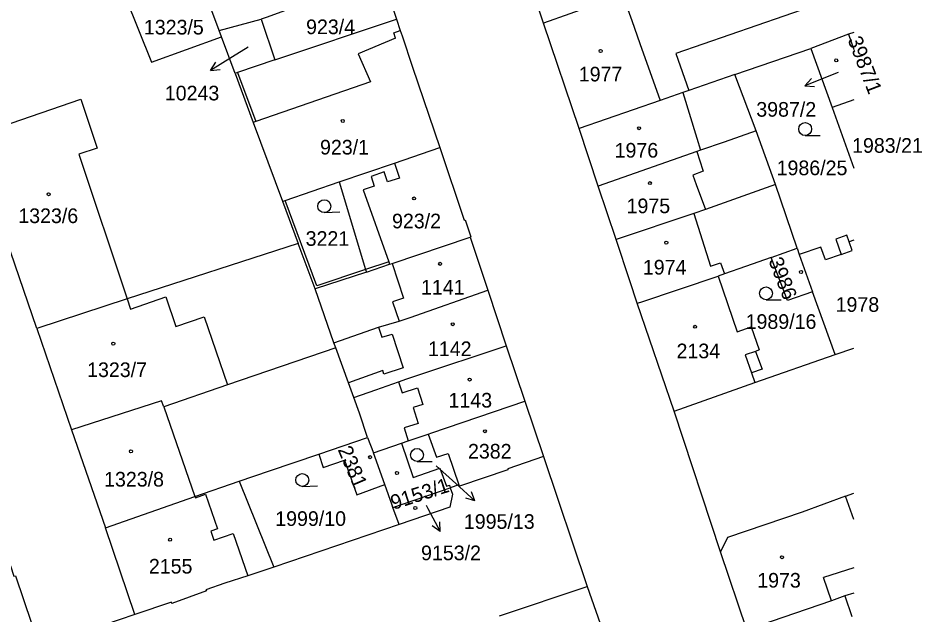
# Model space of a CAD drawing. Extents: x -564952 to -564307, y -1202373 to -1201847.
# Drawn here: x -564411.7 to -564306.7, y -1202091.3 to -1202022 of the extents above; entities that cross this region are included whole.
import ezdxf

# ---------------------------------------------------------------- set-up
doc = ezdxf.new("R2010")
doc.units = 0
for name, color, linetype in [('Hranice parcel', 7, 'Continuous'), ('Parcelní čísla', 7, 'Continuous'), ('Pop  PČ popisy', 7, 'Continuous'), ('Vnitřní kresba', 7, 'Continuous'), ('Značky budov', 7, 'Continuous'), ('Značky kultur', 7, 'Continuous')]:
    doc.layers.add(name, color=color, linetype=linetype)

msp = doc.modelspace()

# ---------------------------------------------------------------- linework, layer by layer
at = {"layer": 'Hranice parcel'}
for p, q in [((-564350.68, -1202022.6), (-564353.91, -1202012.99)), ((-564388.33, -1202023.43), (-564391.22, -1202015.7)), ((-564369.43, -1202017.02), (-564367.73, -1202022.14)), ((-564388.33, -1202023.43), (-564383.43, -1202022.13)), ((-564383.43, -1202022.13), (-564381.84, -1202026.87)), ((-564381.84, -1202026.87), (-564367.73, -1202022.14)), ((-564346.52, -1202034.83), (-564350.68, -1202022.6)), ((-564315.26, -1202023.89), (-564319.63, -1202025.52)), ((-564314.65, -1202023.66), (-564315.26, -1202023.89)), ((-564315.26, -1202023.89), (-564314.65, -1202025.64)), ((-564328.44, -1202028.56), (-564319.63, -1202025.52)), ((-564319.63, -1202025.52), (-564317.17, -1202032.38)), ((-564325.97, -1202035.09), (-564328.44, -1202028.56)), ((-564314.65, -1202031.48), (-564317.17, -1202032.38)), ((-564317.17, -1202032.38), (-564314.65, -1202039.42)), ((-564344.32, -1202041.5), (-564346.52, -1202034.83)), ((-564409.49, -1202058.02), (-564417.13, -1202035.78)), ((-564323.72, -1202041.34), (-564325.97, -1202035.09)), ((-564342.24, -1202047.7), (-564344.32, -1202041.5)), ((-564321.21, -1202048.72), (-564323.72, -1202041.34)), ((-564380.96, -1202043.26), (-564379.14, -1202048.15)), ((-564359.18, -1202047.43), (-564357.14, -1202053.6)), ((-564379.14, -1202048.15), (-564399, -1202054.61)), ((-564377.16, -1202053.45), (-564379.14, -1202048.15)), ((-564324.22, -1202049.78), (-564321.21, -1202048.72)), ((-564321.21, -1202048.72), (-564320.97, -1202049.46)), ((-564320.97, -1202049.46), (-564319.42, -1202053.78)), ((-564371.23, -1202051.48), (-564377.16, -1202053.45)), ((-564375, -1202059.69), (-564377.16, -1202053.45)), ((-564357.14, -1202053.6), (-564354.99, -1202060.04)), ((-564316.8, -1202061.07), (-564319.42, -1202053.78)), ((-564399, -1202054.61), (-564409.49, -1202058.02)), ((-564335.5, -1202067.64), (-564339.78, -1202055.09)), ((-564409.49, -1202058.02), (-564405.45, -1202069.78)), ((-564374.79, -1202060.27), (-564375, -1202059.69)), ((-564354.99, -1202060.04), (-564352.85, -1202066.48)), ((-564373.3, -1202064.33), (-564374.79, -1202060.27)), ((-564326.14, -1202064.32), (-564316.8, -1202061.07)), ((-564316.8, -1202061.07), (-564314.65, -1202060.33)), ((-564372.69, -1202066.04), (-564373.3, -1202064.33)), ((-564372.69, -1202066.04), (-564370.13, -1202065.15)), ((-564335.5, -1202067.64), (-564326.14, -1202064.32)), ((-564395, -1202066.42), (-564405.45, -1202069.78)), ((-564352.85, -1202066.48), (-564350.67, -1202072.89)), ((-564330.1, -1202083.96), (-564335.5, -1202067.64)), ((-564405.45, -1202069.78), (-564401.53, -1202081.18)), ((-564376.76, -1202072.61), (-564371.08, -1202070.67)), ((-564371.08, -1202070.67), (-564370.4, -1202072.46)), ((-564370.4, -1202072.46), (-564367.17, -1202071.36)), ((-564369.09, -1202076.15), (-564370.4, -1202072.46)), ((-564350.67, -1202072.89), (-564345.58, -1202087.99)), ((-564386.01, -1202075.77), (-564381.99, -1202085.72)), ((-564368.14, -1202078.82), (-564361.49, -1202076.51)), ((-564360.5, -1202076.17), (-564361.49, -1202076.51)), ((-564315.61, -1202077.5), (-564314.65, -1202077.16)), ((-564314.65, -1202080.21), (-564315.61, -1202077.5)), ((-564367.44, -1202080.79), (-564368.14, -1202078.82)), ((-564367.44, -1202080.79), (-564381.99, -1202085.72)), ((-564398.11, -1202091.24), (-564401.53, -1202081.18)), ((-564327.05, -1202093.01), (-564330.1, -1202083.96)), ((-564355.78, -1202091.38), (-564345.58, -1202087.99)), ((-564345.58, -1202087.99), (-564343.21, -1202094.78)), ((-564398.11, -1202091.24), (-564409.17, -1202094.97))]:
    msp.add_line(p, q, dxfattribs=at)
for points in [[(-564369.43, -1202017.02), (-564382.88, -1202021.93), (-564383.43, -1202022.13)], [(-564334.61, -1202016.87), (-564340.12, -1202018.83), (-564341.48, -1202019.32), (-564350.68, -1202022.6)], [(-564367.73, -1202022.14), (-564367.3, -1202023.45), (-564367.09, -1202024.07), (-564365.86, -1202027.72), (-564362.71, -1202037.02)], [(-564386.47, -1202028.42), (-564388.06, -1202024.17), (-564388.33, -1202023.43)], [(-564381.84, -1202026.87), (-564386.19, -1202028.32), (-564386.47, -1202028.42)], [(-564386.47, -1202028.42), (-564384.36, -1202034.12), (-564380.96, -1202043.26)], [(-564328.44, -1202028.56), (-564333.81, -1202030.42), (-564334.5, -1202030.66), (-564337.12, -1202031.57), (-564346.52, -1202034.83)], [(-564417.13, -1202035.78), (-564404.38, -1202031.4), (-564402.49, -1202037.11), (-564404.61, -1202037.8), (-564399, -1202054.61)], [(-564325.97, -1202035.09), (-564329.7, -1202036.39), (-564332.45, -1202037.35), (-564332.88, -1202037.5)], [(-564374.39, -1202041.02), (-564367.97, -1202038.83), (-564362.71, -1202037.02)], [(-564362.71, -1202037.02), (-564359.86, -1202045.45), (-564359.77, -1202045.41), (-564359.11, -1202047.41), (-564359.18, -1202047.43)], [(-564332.88, -1202037.5), (-564334.29, -1202037.99), (-564344.32, -1202041.5)], [(-564380.96, -1202043.26), (-564380.67, -1202043.16), (-564374.39, -1202041.02)], [(-564374.39, -1202041.02), (-564371.32, -1202051.19), (-564371.23, -1202051.48)], [(-564323.72, -1202041.34), (-564331.87, -1202044.22), (-564333.22, -1202044.67), (-564342.24, -1202047.7)], [(-564371.23, -1202051.48), (-564368.54, -1202050.58), (-564368.25, -1202050.48), (-564359.18, -1202047.43)], [(-564314.65, -1202047.79), (-564315.19, -1202047.98), (-564315.45, -1202047.21), (-564316.72, -1202047.65), (-564316.1, -1202049.44), (-564317.93, -1202050.07), (-564318.45, -1202048.6), (-564320.97, -1202049.46)], [(-564339.78, -1202055.09), (-564340.65, -1202052.49), (-564342.24, -1202047.7)], [(-564324.22, -1202049.78), (-564327.2, -1202050.83), (-564329.66, -1202051.7), (-564330.39, -1202051.96)], [(-564319.42, -1202053.78), (-564322.34, -1202054.77), (-564324.22, -1202049.78)], [(-564339.78, -1202055.09), (-564339.38, -1202054.96), (-564330.39, -1202051.96)], [(-564330.39, -1202051.96), (-564328.17, -1202058.42), (-564326.54, -1202057.86), (-564325.62, -1202060.53), (-564326.04, -1202060.69), (-564325.28, -1202062.75), (-564326.53, -1202063.18), (-564326.14, -1202064.32)], [(-564375, -1202059.69), (-564369.82, -1202057.88), (-564367.43, -1202057.19), (-564366.16, -1202056.77), (-564357.14, -1202053.6)], [(-564366.54, -1202063.89), (-564365.72, -1202063.6), (-564354.99, -1202060.04)], [(-564374.79, -1202060.27), (-564387.35, -1202064.59), (-564394.75, -1202067.13), (-564395, -1202066.42)], [(-564370.13, -1202065.15), (-564367.49, -1202064.22), (-564366.54, -1202063.89)], [(-564371.08, -1202070.67), (-564372.03, -1202067.88), (-564372.69, -1202066.04)], [(-564364.04, -1202070.29), (-564363.64, -1202070.15), (-564352.85, -1202066.48)], [(-564367.17, -1202071.36), (-564366.37, -1202071.08), (-564364.04, -1202070.29)], [(-564364.04, -1202070.29), (-564363.08, -1202072.97), (-564361.73, -1202072.53), (-564360.5, -1202076.17)], [(-564367.17, -1202071.36), (-564365.78, -1202075.33), (-564362.69, -1202074.26), (-564361.94, -1202076.34), (-564361.59, -1202076.22), (-564361.49, -1202076.51)], [(-564386.01, -1202075.77), (-564382.48, -1202074.57), (-564376.76, -1202072.61)], [(-564376.76, -1202072.61), (-564376.23, -1202074.16), (-564373.75, -1202073.3), (-564372.35, -1202077.33), (-564369.09, -1202076.15)], [(-564350.67, -1202072.89), (-564354.81, -1202074.32), (-564354.8, -1202074.43), (-564360.43, -1202076.34), (-564360.5, -1202076.17)], [(-564401.53, -1202081.18), (-564391.13, -1202077.52), (-564386.01, -1202075.77)], [(-564368.14, -1202078.82), (-564368.24, -1202078.54), (-564369.09, -1202076.15)], [(-564361.49, -1202076.51), (-564361.22, -1202077.28), (-564361.53, -1202078.76), (-564367.44, -1202080.79)], [(-564315.61, -1202077.5), (-564320.65, -1202079.34), (-564329.31, -1202082.28), (-564330.1, -1202083.96)], [(-564412.56, -1202085.59), (-564412.16, -1202086.79), (-564411.96, -1202086.73), (-564409.17, -1202094.97)], [(-564381.99, -1202085.72), (-564385, -1202086.73), (-564387.67, -1202087.58)], [(-564387.67, -1202087.58), (-564389.85, -1202088.36), (-564389.8, -1202088.5), (-564393.82, -1202089.94), (-564393.87, -1202089.8), (-564398.11, -1202091.24)], [(-564314.65, -1202088.74), (-564315.68, -1202089.06), (-564317.24, -1202089.63), (-564327.05, -1202093.01)]]:
    msp.add_lwpolyline(points, dxfattribs=at)
at = {"layer": 'Pop  PČ popisy'}
for p, q in [((-564384.96, -1202025.38), (-564386.76, -1202026.49)), ((-564386.76, -1202026.49), (-564389.31, -1202028.08)), ((-564389.31, -1202028.08), (-564388.72, -1202027.12)), ((-564389.31, -1202028.08), (-564388.19, -1202027.97)), ((-564316.46, -1202028.33), (-564317.53, -1202028.75)), ((-564317.53, -1202028.75), (-564320.31, -1202029.87)), ((-564320.31, -1202029.87), (-564319.57, -1202029.03)), ((-564320.31, -1202029.87), (-564319.2, -1202029.96)), ((-564363.13, -1202073.97), (-564360.85, -1202076.03)), ((-564360.85, -1202076.03), (-564358.62, -1202078.04)), ((-564358.62, -1202078.04), (-564359.7, -1202077.74)), ((-564358.62, -1202078.04), (-564359.03, -1202077)), ((-564364.29, -1202078.55), (-564364.08, -1202078.93)), ((-564364.08, -1202078.93), (-564362.67, -1202081.58)), ((-564362.67, -1202081.58), (-564363.58, -1202080.93)), ((-564362.67, -1202081.58), (-564362.7, -1202080.46))]:
    msp.add_line(p, q, dxfattribs=at)
at = {"layer": 'Vnitřní kresba'}
for p, q in [((-564399.49, -1202018.85), (-564396.18, -1202027.14)), ((-564341.48, -1202019.32), (-564340.42, -1202022.3)), ((-564319.62, -1202020.68), (-564335.3, -1202026.12)), ((-564340.42, -1202022.3), (-564339.48, -1202024.94)), ((-564396.18, -1202027.14), (-564388.06, -1202024.17)), ((-564367.85, -1202024.33), (-564372.18, -1202026.14)), ((-564368.06, -1202023.7), (-564367.3, -1202023.45)), ((-564367.85, -1202024.33), (-564368.06, -1202023.7)), ((-564339.48, -1202024.94), (-564337.12, -1202031.57)), ((-564372.18, -1202026.14), (-564370.75, -1202029.4)), ((-564335.3, -1202026.12), (-564333.81, -1202030.42)), ((-564386.19, -1202028.32), (-564384.08, -1202034.02)), ((-564370.75, -1202029.4), (-564384.08, -1202034.02)), ((-564334.5, -1202030.66), (-564332.88, -1202035.95)), ((-564384.08, -1202034.02), (-564384.36, -1202034.12)), ((-564332.88, -1202035.95), (-564332.45, -1202037.35)), ((-564332.88, -1202037.5), (-564332.16, -1202039.65)), ((-564367.97, -1202038.83), (-564367.38, -1202040.58)), ((-564369.15, -1202039.85), (-564370.69, -1202040.4)), ((-564368.78, -1202041.02), (-564369.15, -1202039.85)), ((-564332.11, -1202039.79), (-564333.34, -1202040.22)), ((-564332.16, -1202039.65), (-564332.11, -1202039.79)), ((-564370.69, -1202040.4), (-564370.34, -1202041.52)), ((-564367.38, -1202040.58), (-564368.78, -1202041.02)), ((-564333.34, -1202040.22), (-564332.93, -1202041.33)), ((-564370.34, -1202041.52), (-564371.62, -1202041.93)), ((-564371.62, -1202041.93), (-564368.64, -1202050.3)), ((-564332.93, -1202041.33), (-564331.87, -1202044.22)), ((-564376.98, -1202053.07), (-564380.67, -1202043.16)), ((-564333.22, -1202044.67), (-564331.27, -1202050.8)), ((-564314.83, -1202049), (-564315.19, -1202047.98)), ((-564316.1, -1202049.44), (-564314.83, -1202049)), ((-564368.64, -1202050.3), (-564371.32, -1202051.19)), ((-564368.64, -1202050.3), (-564368.54, -1202050.58)), ((-564368.25, -1202050.48), (-564366.91, -1202054.51)), ((-564331.27, -1202050.8), (-564330.11, -1202050.41)), ((-564330.11, -1202050.41), (-564329.66, -1202051.7)), ((-564371.32, -1202051.19), (-564376.98, -1202053.07)), ((-564399, -1202054.61), (-564398.6, -1202055.8)), ((-564398.6, -1202055.8), (-564394.52, -1202054.37)), ((-564394.52, -1202054.37), (-564393.37, -1202057.8)), ((-564366.91, -1202054.51), (-564368.18, -1202054.93)), ((-564368.18, -1202054.93), (-564367.43, -1202057.19)), ((-564393.37, -1202057.8), (-564390.06, -1202056.69)), ((-564390.06, -1202056.69), (-564387.35, -1202064.59)), ((-564369.82, -1202057.88), (-564369.44, -1202059.04)), ((-564369.44, -1202059.04), (-564368.24, -1202058.71)), ((-564368.24, -1202058.71), (-564366.96, -1202062.61)), ((-564326.04, -1202060.69), (-564327.25, -1202061.11)), ((-564327.25, -1202061.11), (-564326.53, -1202063.18)), ((-564369.3, -1202062.91), (-564373.3, -1202064.33)), ((-564369.22, -1202063.35), (-564369.3, -1202062.91)), ((-564366.96, -1202062.61), (-564369.22, -1202063.35)), ((-564367.49, -1202064.22), (-564367.08, -1202065.5)), ((-564367.08, -1202065.5), (-564365.3, -1202064.93)), ((-564365.3, -1202064.93), (-564364.69, -1202066.84)), ((-564394.75, -1202067.13), (-564391.13, -1202077.52)), ((-564364.69, -1202066.84), (-564365.79, -1202067.19)), ((-564365.79, -1202067.19), (-564365.2, -1202069.05)), ((-564365.2, -1202069.05), (-564366.85, -1202069.57)), ((-564366.85, -1202069.57), (-564366.37, -1202071.08)), ((-564391.13, -1202077.52), (-564391.07, -1202077.68)), ((-564391.07, -1202077.68), (-564389.91, -1202077.27)), ((-564389.91, -1202077.27), (-564388.51, -1202081.29)), ((-564388.51, -1202081.29), (-564389.28, -1202081.55)), ((-564389.28, -1202081.55), (-564388.92, -1202082.59)), ((-564388.92, -1202082.59), (-564386.71, -1202081.82)), ((-564386.71, -1202081.82), (-564385, -1202086.73)), ((-564314.65, -1202085.82), (-564318.14, -1202086.92)), ((-564317.24, -1202089.63), (-564318.14, -1202086.92)), ((-564315.68, -1202089.06), (-564314.87, -1202091.46))]:
    msp.add_line(p, q, dxfattribs=at)
at = {"layer": 'Značky budov'}
for centre in [(-564344.03, -1202025.82), (-564316.68, -1202026.91), (-564373.97, -1202033.95), (-564339.57, -1202034.79), (-564338.31, -1202041.16), (-564408.12, -1202042.45), (-564365.69, -1202042.94), (-564336.41, -1202048.07), (-564362.67, -1202050.53), (-564320.77, -1202051.47), (-564361.2, -1202057.54), (-564333.06, -1202057.84), (-564400.61, -1202059.79), (-564359.24, -1202063.96), (-564357.47, -1202069.96), (-564398.56, -1202072.29), (-564370.8, -1202072.97), (-564367.68, -1202074.8), (-564365.55, -1202078.87), (-564394.02, -1202082.55), (-564322.98, -1202084.58)]:
    msp.add_circle(centre, 0.175, dxfattribs=at)
at = {"layer": 'Značky kultur'}
for p, q in [((-564320.29, -1202035.64), (-564318.54, -1202035.64)), ((-564376.08, -1202044.59), (-564374.33, -1202044.5)), ((-564324.83, -1202054.7), (-564323.08, -1202054.7)), ((-564365.35, -1202073.46), (-564363.6, -1202073.46)), ((-564378.63, -1202076.37), (-564376.89, -1202076.28))]:
    msp.add_line(p, q, dxfattribs=at)
for centre in [(-564320.29, -1202034.89), (-564376.12, -1202043.84), (-564324.83, -1202053.95), (-564365.35, -1202072.71), (-564378.67, -1202075.62)]:
    msp.add_circle(centre, 0.75, dxfattribs=at)

# ---------------------------------------------------------------- texts
at = {"layer": 'Parcelní čísla'}
for s, p in [('1323/5', (-564397.06, -1202023.91)), ('923/4', (-564378.23, -1202023.87)), ('1977', (-564346.57, -1202029.36)), ('10243', (-564394.63, -1202031.56)), ('3987/2', (-564325.96, -1202033.45)), ('1983/21', (-564314.84, -1202037.64)), ('923/1', (-564376.61, -1202037.84)), ('1976', (-564342.41, -1202038.2)), ('1986/25', (-564323.6, -1202040.24)), ('1975', (-564341.02, -1202044.65)), ('1323/6', (-564411.64, -1202045.8)), ('923/2', (-564368.25, -1202046.41)), ('3221', (-564378.28, -1202048.44)), ('1974', (-564339.13, -1202051.77)), ('1141', (-564364.89, -1202054.09)), ('1978', (-564316.75, -1202056.1)), ('1989/16', (-564327.2, -1202058.08)), ('1142', (-564364.08, -1202061.24)), ('2134', (-564335.22, -1202061.49)), ('1323/7', (-564403.65, -1202063.67)), ('1143', (-564361.69, -1202067.21)), ('2382', (-564359.43, -1202073.13)), ('1323/8', (-564401.68, -1202076.38)), ('1999/10', (-564381.81, -1202080.95)), ('1995/13', (-564359.91, -1202081.29)), ('9153/2', (-564364.88, -1202084.93)), ('2155', (-564396.48, -1202086.48)), ('1973', (-564325.85, -1202088.11))]:
    msp.add_text(s, height=1.7, dxfattribs=at).set_placement(p)
for s, rotation, p in [('3987/1', 291, (-564315.38, -1202024.49)), ('3986', 291, (-564324.57, -1202050.14)), ('2381', 293, (-564374.58, -1202072.09)), ('9153/1', 18, (-564368.09, -1202079.1))]:
    msp.add_text(s, height=1.7, rotation=rotation, dxfattribs=at).set_placement(p)

doc.saveas('drawing.dxf')
